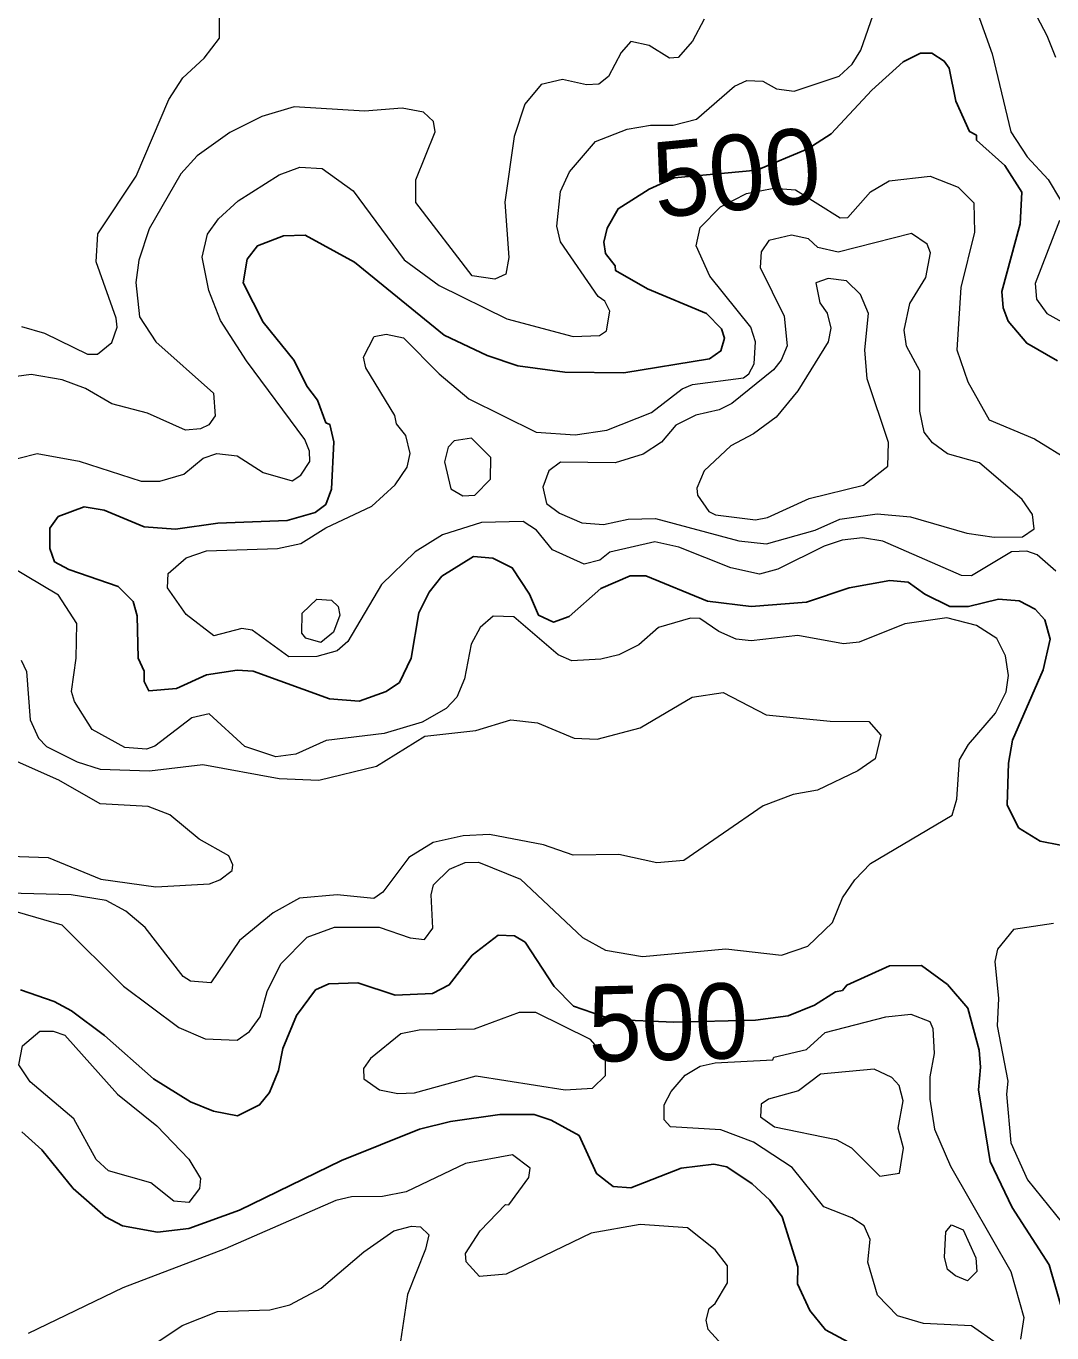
# Model space of a CAD drawing. Extents: x 763.2 to 816.8, y 7896.5 to 7952.7.
# Drawn here: x 779.613 to 781.792, y 7907.874 to 7910.648 of the extents above; entities that cross this region are included whole.
import ezdxf
from ezdxf.enums import TextEntityAlignment as Align

# ---------------------------------------------------------------- set-up
doc = ezdxf.new("R2010")
doc.units = 0
doc.header["$LTSCALE"] = 0.064
doc.layers.add('1', color=7, linetype='Continuous', lineweight=25)
doc.layers.add('2', color=7, linetype='Continuous', lineweight=13)
doc.layers.add('61', color=7, linetype='Continuous')

msp = doc.modelspace()

# ---------------------------------------------------------------- linework, layer by layer
at = {"layer": '1'}
for points in [[(781.4758, 7910.5721), (781.5125, 7910.5906), (781.5364, 7910.5906), (781.5631, 7910.5739), (781.5733, 7910.5587), (781.5874, 7910.4891), (781.617, 7910.4244), (781.6316, 7910.4166), (781.6316, 7910.4063), (781.6916, 7910.3522), (781.7276, 7910.2957), (781.7242, 7910.2285), (781.6852, 7910.0845), (781.6881, 7910.0502), (781.6986, 7910.0217), (781.7383, 7909.9751), (781.8035, 7909.9376)], [(780.9899, 7910.3261), (781.1652, 7910.342), (781.2732, 7910.3878), (781.3228, 7910.4194), (781.4094, 7910.5124), (781.4758, 7910.5721)], [(781.7665, 7908.9181), (781.7206, 7908.9465), (781.6966, 7908.9952), (781.6997, 7909.0835), (781.7079, 7909.1324), (781.7734, 7909.2819), (781.788, 7909.3466), (781.7765, 7909.3879), (781.756, 7909.4103), (781.7219, 7909.4284), (781.6784, 7909.432), (781.6145, 7909.4161), (781.5748, 7909.4161), (781.5219, 7909.4424), (781.4867, 7909.4678), (781.4476, 7909.4714), (781.3612, 7909.4555), (781.2708, 7909.4256), (781.1533, 7909.4158), (781.0605, 7909.4272), (780.9297, 7909.4811), (780.8962, 7909.4814), (780.8335, 7909.4543), (780.7668, 7909.3949), (780.733, 7909.3829), (780.7013, 7909.3974), (780.6822, 7909.4425), (780.6457, 7909.4982), (780.6043, 7909.5189), (780.5637, 7909.5225), (780.4964, 7909.4806), (780.469, 7909.4468), (780.4472, 7909.4026), (780.4311, 7909.3064), (780.4061, 7909.2548), (780.3781, 7909.2358), (780.3209, 7909.2154), (780.2578, 7909.2204), (780.0957, 7909.2787), (780.0613, 7909.2809), (779.9963, 7909.2712), (779.9331, 7909.2417), (779.874, 7909.2374), (779.8642, 7909.2571), (779.8639, 7909.2787), (779.8512, 7909.3064), (779.8494, 7909.396), (779.8408, 7909.427), (779.809, 7909.4587), (779.7038, 7909.4944), (779.6739, 7909.5111), (779.6636, 7909.5391), (779.6637, 7909.5825), (779.6817, 7909.6073), (779.7366, 7909.6276), (779.7792, 7909.6207), (779.8642, 7909.585), (779.9306, 7909.5801), (780.0202, 7909.5933), (780.1681, 7909.5984), (780.2273, 7909.6157), (780.2501, 7909.6328), (780.2616, 7909.6655), (780.2666, 7909.7657), (780.2587, 7909.8024), (780.2502, 7909.806), (780.2324, 7909.8538), (780.2092, 7909.8841), (780.1827, 7909.9382), (780.1171, 7910.02), (780.0745, 7910.1034), (780.0828, 7910.1535), (780.1045, 7910.1817), (780.16, 7910.2027), (780.2059, 7910.2043), (780.311, 7910.147), (780.5008, 7909.9922), (780.5923, 7909.9488), (780.6579, 7909.9272), (780.7574, 7909.9137), (780.883, 7909.9121), (781.0643, 7909.9422), (781.0883, 7909.9586), (781.0963, 7909.986), (781.0898, 7910.0054), (781.0585, 7910.0384), (780.933, 7910.0908), (780.8653, 7910.1292), (780.8644, 7910.1394), (780.8438, 7910.1653), (780.8404, 7910.1897), (780.847, 7910.2194), (780.8705, 7910.2605), (780.9363, 7910.3017), (780.9899, 7910.3261)], [(781.8962, 7908.8928), (781.7665, 7908.9181)], [(780.1495, 7908.4314), (780.1585, 7908.4781), (780.1873, 7908.548), (780.2281, 7908.6024), (780.2559, 7908.6153), (780.3176, 7908.617), (780.3973, 7908.5908), (780.4761, 7908.5944), (780.5121, 7908.6127), (780.5609, 7908.6761), (780.6159, 7908.7187), (780.6508, 7908.7169), (780.6729, 7908.7038), (780.7347, 7908.6094), (780.7756, 7908.5676), (780.8579, 7908.5396), (780.9891, 7908.5338), (781.1625, 7908.5377), (781.2319, 7908.5472), (781.2873, 7908.5695), (781.3318, 7908.598), (781.3467, 7908.6012), (781.3559, 7908.6126), (781.4468, 7908.653), (781.5145, 7908.6541), (781.57, 7908.6137), (781.6134, 7908.5638), (781.6373, 7908.474), (781.6402, 7908.438), (781.6357, 7908.3902), (781.6603, 7908.2381), (781.7072, 7908.1402), (781.7858, 7908.0188), (781.8159, 7907.915)], [(779.6012, 7908.6022), (779.6727, 7908.5777), (779.7096, 7908.5578), (779.7796, 7908.5057), (779.8839, 7908.4133), (779.9627, 7908.3649), (780.0113, 7908.3445), (780.0623, 7908.3346), (780.1091, 7908.3581), (780.1306, 7908.3844), (780.1495, 7908.4314)], [(781.3597, 7907.8545), (781.3106, 7907.8809), (781.2775, 7907.9219), (781.2514, 7907.9782), (781.2525, 7908.0145), (781.2188, 7908.1206), (781.1926, 7908.1561), (781.155, 7908.1903), (781.1011, 7908.2267), (781.0739, 7908.2323), (781.0047, 7908.224), (780.8978, 7908.1819), (780.8601, 7908.185), (780.8244, 7908.2124), (780.7875, 7908.2931), (780.7285, 7908.326), (780.6924, 7908.3375), (780.6193, 7908.3375), (780.5149, 7908.3227), (780.4491, 7908.3063), (780.2832, 7908.2399), (780.0663, 7908.1348), (779.9587, 7908.0958), (779.8921, 7908.088), (779.8178, 7908.1017), (779.782, 7908.1207), (779.7134, 7908.1809), (779.6465, 7908.2625), (779.6044, 7908.3013)]]:
    msp.add_lwpolyline(points, dxfattribs=at)
at = {"layer": '2'}
for points in [[(781.7998, 7910.5816), (781.7816, 7910.6276), (781.7046, 7910.7748)], [(779.6037, 7910.0107), (779.6528, 7909.9964), (779.7437, 7909.9515), (779.7653, 7909.9517), (779.7957, 7909.9767), (779.8065, 7910.0092), (779.8049, 7910.0281), (779.7619, 7910.1481), (779.7657, 7910.2071), (779.8468, 7910.3297), (779.9167, 7910.4921), (779.9463, 7910.5381), (779.9916, 7910.5804), (780.0241, 7910.6223), (780.0242, 7910.6713)], [(780.0265, 7910.0233), (780.0015, 7910.0868), (779.9874, 7910.1576), (779.9989, 7910.2062), (780.0219, 7910.2389), (780.0636, 7910.2775), (780.1511, 7910.3323), (780.1944, 7910.349), (780.242, 7910.3457), (780.3078, 7910.2982), (780.4161, 7910.1521), (780.4903, 7910.0978), (780.6343, 7910.0265), (780.7752, 7909.9892), (780.8309, 7909.9913), (780.846, 7910.0014), (780.8528, 7910.0428), (780.842, 7910.0643), (780.8279, 7910.0745), (780.7481, 7910.1904), (780.7401, 7910.2233), (780.7485, 7910.2974), (780.7672, 7910.3388), (780.8227, 7910.4032), (780.8896, 7910.4296), (780.9396, 7910.4379), (780.9876, 7910.4379), (781.0369, 7910.4508), (781.1175, 7910.5204), (781.144, 7910.5329), (781.1779, 7910.5315), (781.2066, 7910.5148), (781.2446, 7910.5103), (781.3398, 7910.5416), (781.3675, 7910.5674), (781.3859, 7910.5974), (781.4172, 7910.686)], [(781.6306, 7910.6844), (781.6646, 7910.5896), (781.7046, 7910.4239), (781.7393, 7910.3706), (781.7834, 7910.3228), (781.8097, 7910.2785)], [(781.0533, 7910.6626), (781.0288, 7910.6165), (780.9978, 7910.5816), (780.9799, 7910.58), (780.9365, 7910.6072), (780.8975, 7910.6153), (780.8768, 7910.5921), (780.85, 7910.5415), (780.8297, 7910.5251), (780.8037, 7910.5234), (780.7527, 7910.5349), (780.7069, 7910.5244), (780.6723, 7910.4827), (780.6498, 7910.4139), (780.63, 7910.2745), (780.6382, 7910.1569), (780.6321, 7910.1218), (780.6089, 7910.1109), (780.5609, 7910.1182), (780.441, 7910.2739), (780.4412, 7910.3221), (780.482, 7910.4237), (780.4788, 7910.4455), (780.4571, 7910.4654), (780.4123, 7910.474), (780.3318, 7910.4676), (780.1825, 7910.477), (780.114, 7910.456), (780.0462, 7910.4221), (779.9763, 7910.3727), (779.942, 7910.3347), (779.875, 7910.2179), (779.8528, 7910.151), (779.8462, 7910.1036), (779.8544, 7910.031), (779.8888, 7909.9776), (780.0116, 7909.869), (780.0152, 7909.8212), (780.0013, 7909.8017), (779.9834, 7909.7932), (779.9517, 7909.7907), (779.8713, 7909.8262), (779.7955, 7909.8462), (779.7392, 7909.879), (779.6899, 7909.8972), (779.6239, 7909.9088), (779.5772, 7909.9021)], [(781.7997, 7909.4909), (781.7604, 7909.5258), (781.7384, 7909.5337), (781.7059, 7909.5319), (781.621, 7909.4815), (781.5997, 7909.4817), (781.4326, 7909.5551), (781.3897, 7909.562), (781.3464, 7909.557), (781.3084, 7909.5443), (781.2098, 7909.4952), (781.1704, 7909.485), (781.1098, 7909.4979), (780.9996, 7909.5422), (780.9487, 7909.5537), (780.853, 7909.5311), (780.8318, 7909.5144), (780.7984, 7909.5063), (780.7315, 7909.5362), (780.6972, 7909.5784), (780.6691, 7909.5962), (780.5807, 7909.5947), (780.4978, 7909.5681), (780.4394, 7909.5323), (780.3679, 7909.4628), (780.2963, 7909.3418), (780.274, 7909.3219), (780.2307, 7909.3103), (780.1711, 7909.3093), (780.0935, 7909.3662), (780.0714, 7909.3693), (780.0122, 7909.3535), (779.9533, 7909.3989), (779.9135, 7909.456), (779.9154, 7909.486), (779.9535, 7909.5194), (779.9963, 7909.534), (780.147, 7909.5394), (780.1971, 7909.5497), (780.2497, 7909.5829), (780.3472, 7909.6294), (780.3969, 7909.6743), (780.4227, 7909.7119), (780.4292, 7909.7408), (780.4199, 7909.7793), (780.3997, 7909.8042), (780.3962, 7909.8215), (780.3345, 7909.9229), (780.3299, 7909.9457), (780.3526, 7909.989), (780.3783, 7909.994), (780.4146, 7909.9866), (780.4908, 7909.9099), (780.5538, 7909.8566), (780.6967, 7909.7863), (780.7793, 7909.7806), (780.8468, 7909.7904), (780.9416, 7909.8278), (781.0068, 7909.8782), (781.0286, 7909.8873), (781.1365, 7909.9018), (781.1484, 7909.9103), (781.1594, 7909.9309), (781.1624, 7909.978), (781.1524, 7910.0089), (781.0655, 7910.1175), (781.0363, 7910.1818), (781.0445, 7910.2209), (781.0879, 7910.2644), (781.1434, 7910.2927), (781.2011, 7910.3041), (781.2471, 7910.3005), (781.3418, 7910.241), (781.3582, 7910.2422), (781.4063, 7910.2967), (781.4459, 7910.32), (781.5332, 7910.3294), (781.5927, 7910.3065), (781.6258, 7910.2728), (781.6276, 7910.2109), (781.5983, 7910.0934), (781.5897, 7909.9609), (781.6131, 7909.8933), (781.6585, 7909.8126), (781.7546, 7909.7719), (781.8301, 7909.7256)], [(781.808, 7910.2353), (781.7559, 7910.1017), (781.7591, 7910.0682), (781.7809, 7910.0382), (781.8573, 7909.9958)], [(780.197, 7909.6947), (780.2156, 7909.7242), (780.2155, 7909.7459), (780.2056, 7909.7705), (780.0815, 7909.9377), (780.0265, 7910.0233)], [(779.5589, 7909.7214), (779.6367, 7909.7409), (779.726, 7909.7246), (779.8577, 7909.682), (779.8976, 7909.6822), (779.9482, 7909.6968), (779.9892, 7909.7311), (780.0186, 7909.741), (780.0613, 7909.7359), (780.1167, 7909.7004), (780.1782, 7909.6828), (780.197, 7909.6947)], [(780.0619, 7908.4956), (780.0878, 7908.5138), (780.1105, 7908.5454), (780.1254, 7908.5989), (780.1546, 7908.6574), (780.2105, 7908.7142), (780.2684, 7908.7353), (780.3631, 7908.7354), (780.4288, 7908.7125), (780.4593, 7908.7095), (780.4769, 7908.7332), (780.4738, 7908.8043), (780.4788, 7908.8256), (780.5128, 7908.8586), (780.5456, 7908.8729), (780.5739, 7908.8731), (780.6635, 7908.8374), (780.7948, 7908.7133), (780.8435, 7908.6863), (780.9225, 7908.6729), (781.0993, 7908.6891), (781.2177, 7908.6762), (781.2735, 7908.6952), (781.3261, 7908.745), (781.3473, 7908.7974), (781.3732, 7908.836), (781.4062, 7908.8705), (781.5802, 7908.9731), (781.5896, 7909.007), (781.5958, 7909.0908), (781.6144, 7909.1231), (781.6716, 7909.1895), (781.6943, 7909.2352), (781.6997, 7909.2694), (781.6934, 7909.3111), (781.6748, 7909.3481), (781.6312, 7909.3759), (781.5687, 7909.3919), (781.4796, 7909.3792), (781.3826, 7909.3401), (781.3491, 7909.3369), (781.2525, 7909.3547), (781.1532, 7909.3435), (781.1212, 7909.3465), (781.0842, 7909.3627), (781.0438, 7909.3908), (781.0243, 7909.391), (780.956, 7909.3713), (780.9146, 7909.3349), (780.8718, 7909.3133), (780.8337, 7909.304), (780.7724, 7909.3006), (780.743, 7909.3135), (780.6488, 7909.3942), (780.605, 7909.3959), (780.5774, 7909.3713), (780.5583, 7909.3365), (780.5443, 7909.2629), (780.5279, 7909.2233), (780.5055, 7909.1996), (780.4544, 7909.1704), (780.3735, 7909.1462), (780.2503, 7909.1318), (780.1863, 7909.1028), (780.1434, 7909.0969), (780.0779, 7909.1186), (780.0023, 7909.1884), (779.965, 7909.1798), (779.8865, 7909.1196), (779.8692, 7909.1133), (779.8227, 7909.1166), (779.7535, 7909.1549), (779.7159, 7909.2142), (779.7098, 7909.2356), (779.7194, 7909.3063), (779.7211, 7909.38), (779.6825, 7909.4405), (779.5792, 7909.5016)], [(779.6026, 7909.3019), (779.6143, 7909.2783), (779.6222, 7909.1755), (779.6394, 7909.1368), (779.6567, 7909.1192), (779.7216, 7909.0864), (779.7706, 7909.0709), (779.8754, 7909.0674), (779.989, 7909.0804), (780.1508, 7909.0509), (780.2348, 7909.0476), (780.3577, 7909.0775), (780.4598, 7909.1412)], [(780.8261, 7909.1342), (780.9173, 7909.1583), (781.0277, 7909.2234), (781.0935, 7909.2333), (781.1846, 7909.1859), (781.3209, 7909.1725), (781.4026, 7909.172), (781.4282, 7909.1427), (781.4163, 7909.0928), (781.3795, 7909.0676), (781.2939, 7909.0262), (781.2425, 7909.0173), (781.1783, 7908.9929), (781.0103, 7908.8768), (780.9527, 7908.8718), (780.8724, 7908.8897), (780.7752, 7908.8881), (780.712, 7908.9104), (780.5977, 7908.9324), (780.5412, 7908.9292), (780.4776, 7908.9151), (780.4263, 7908.8831), (780.3707, 7908.8098), (780.3521, 7908.7963), (780.2742, 7908.8043), (780.1941, 7908.7968), (780.1382, 7908.7656), (780.0662, 7908.7073), (780.0059, 7908.6172), (779.9623, 7908.6205), (779.9472, 7908.6309), (779.8662, 7908.7348), (779.8252, 7908.7694), (779.7833, 7908.7923), (779.709, 7908.8043), (779.5768, 7908.8079)], [(780.4598, 7909.1412), (780.5682, 7909.1529), (780.6426, 7909.1755), (780.699, 7909.169), (780.7772, 7909.1366), (780.8261, 7909.1342)], [(779.4761, 7908.8899), (779.6603, 7908.8832), (779.772, 7908.8372), (779.889, 7908.8208), (780.0028, 7908.8276), (780.025, 7908.8356), (780.0511, 7908.8557), (780.0526, 7908.8674), (780.0438, 7908.8871), (779.9812, 7908.9219), (779.9185, 7908.9742), (779.8723, 7908.9916), (779.7707, 7908.9969), (779.6827, 7909.0478), (779.5952, 7909.0867)], [(779.5945, 7908.7681), (779.6893, 7908.7404), (779.8203, 7908.6099), (779.9375, 7908.5221), (779.9933, 7908.4982), (780.0619, 7908.4956)], [(781.7952, 7908.7434), (781.7098, 7908.7306), (781.6761, 7908.689), (781.6706, 7908.6627), (781.6783, 7908.5838), (781.6753, 7908.5259), (781.6979, 7908.4082), (781.6949, 7908.3812), (781.7047, 7908.2776), (781.74, 7908.1993), (781.8439, 7908.0703)], [(781.6755, 7907.851), (781.621, 7907.889), (781.5188, 7907.8939), (781.4637, 7907.9105), (781.4211, 7907.9542), (781.4007, 7908.0244), (781.4056, 7908.0724), (781.3933, 7908.1014), (781.3666, 7908.1186), (781.3072, 7908.142), (781.2402, 7908.2252), (781.1578, 7908.2791), (781.0887, 7908.305), (780.9818, 7908.3115), (780.9686, 7908.3263), (780.9685, 7908.3581), (780.9834, 7908.3868), (781.0129, 7908.4214), (781.0445, 7908.4405), (781.0763, 7908.4477), (781.199, 7908.4539), (781.2012, 7908.4592), (781.2707, 7908.4758), (781.3104, 7908.5116), (781.4392, 7908.5451), (781.4918, 7908.551), (781.5324, 7908.5354), (781.5391, 7908.5204), (781.542, 7908.4674), (781.5322, 7908.4174), (781.5321, 7908.3705), (781.5421, 7908.3064), (781.5762, 7908.2282), (781.7045, 7908.0046), (781.7323, 7907.9067), (781.7247, 7907.8607)], [(781.1287, 7907.8078), (781.0619, 7907.8811), (781.0577, 7907.9015), (781.064, 7907.9261), (781.0766, 7907.9367), (781.1027, 7907.9803), (781.1031, 7908.0164), (781.0764, 7908.0505), (781.0182, 7908.0972), (780.9177, 7908.1041), (780.8134, 7908.0858), (780.6325, 7907.999), (780.5761, 7907.9936), (780.5479, 7908.0247), (780.5467, 7908.0425), (780.5775, 7908.091), (780.6313, 7908.1468), (780.6388, 7908.1463), (780.6811, 7908.2041), (780.6838, 7908.2239), (780.6461, 7908.2518), (780.5464, 7908.2335), (780.4202, 7908.1734), (780.3702, 7908.1634), (780.3041, 7908.1632), (780.271, 7908.1549), (780.0364, 7908.0523), (779.8187, 7907.9697), (779.6175, 7907.8726)], [(779.8591, 7907.8326), (779.945, 7907.8899), (780.0201, 7907.9199), (780.1313, 7907.9232), (780.1737, 7907.9336), (780.2399, 7907.9688), (780.3303, 7908.0459), (780.3943, 7908.0907), (780.4321, 7908.1007), (780.451, 7908.0994), (780.4683, 7908.0821), (780.4618, 7908.052), (780.423, 7907.9554), (780.4062, 7907.8423)]]:
    msp.add_lwpolyline(points, dxfattribs=at)
for points in [[(781.6379, 7909.7209), (781.5697, 7909.7399), (781.5378, 7909.7637), (781.5202, 7909.7859), (781.511, 7909.8309), (781.5111, 7909.9166), (781.4832, 7909.9686), (781.4781, 7910.0026), (781.4903, 7910.0596), (781.524, 7910.1147), (781.5338, 7910.1671), (781.5267, 7910.1851), (781.4932, 7910.2076), (781.338, 7910.1685), (781.2947, 7910.1785), (781.275, 7910.1963), (781.2386, 7910.2043), (781.1904, 7910.1929), (781.1746, 7910.169), (781.1719, 7910.1357), (781.2228, 7910.0322), (781.2295, 7909.9698), (781.2167, 7909.9387), (781.2002, 7909.9186), (781.1119, 7909.8473), (781.0851, 7909.8333), (781.0354, 7909.8224), (780.9928, 7909.8009), (780.9624, 7909.7649), (780.9236, 7909.7393), (780.864, 7909.7214), (780.7485, 7909.7228), (780.7233, 7909.7042), (780.7106, 7909.6692), (780.7185, 7909.6348), (780.7461, 7909.6139), (780.7938, 7909.594), (780.8396, 7909.5899), (780.8917, 7909.6013), (780.95, 7909.6029), (781.1269, 7909.5552), (781.1855, 7909.5489), (781.2893, 7909.5779), (781.3413, 7909.6017), (781.4207, 7909.6128), (781.4911, 7909.6063), (781.6107, 7909.5717), (781.6693, 7909.5636), (781.7289, 7909.564), (781.7537, 7909.5808), (781.7505, 7909.6111), (781.7285, 7909.6433)], [(781.4434, 7909.7138), (781.445, 7909.7644), (781.3994, 7909.8991), (781.3942, 7909.9611), (781.4021, 7910.0379), (781.3854, 7910.0783), (781.3557, 7910.1074), (781.3163, 7910.1123), (781.2907, 7910.103), (781.299, 7910.0605), (781.3143, 7910.0386), (781.3219, 7910.0069), (781.3165, 7909.9781), (781.2524, 7909.8737), (781.2062, 7909.8179), (781.158, 7909.7825), (781.1099, 7909.7574), (781.0532, 7909.7044), (781.0378, 7909.6671), (781.039, 7909.6521), (781.0632, 7909.6177), (781.077, 7909.611), (781.1624, 7909.5998), (781.1877, 7909.6052), (781.2762, 7909.6451), (781.3919, 7909.6736)], [(780.5594, 7909.7735), (780.5221, 7909.7676), (780.5095, 7909.7544), (780.502, 7909.7232), (780.5153, 7909.6656), (780.5406, 7909.6511), (780.5664, 7909.6522), (780.5996, 7909.6862), (780.6002, 7909.7322)], [(780.2621, 7909.4299), (780.2761, 7909.416), (780.2798, 7909.3979), (780.266, 7909.3615), (780.239, 7909.3399), (780.2071, 7909.3487), (780.1987, 7909.3596), (780.1996, 7909.4022), (780.2306, 7909.4318)], [(780.5692, 7908.4196), (780.7581, 7908.3902), (780.8163, 7908.3935), (780.8434, 7908.4206), (780.844, 7908.4604), (780.8118, 7908.4973), (780.6956, 7908.5543), (780.6607, 7908.5541), (780.5648, 7908.5187), (780.4478, 7908.5166), (780.4092, 7908.5087), (780.3447, 7908.4565), (780.3298, 7908.4356), (780.3303, 7908.4134), (780.3639, 7908.3901), (780.4025, 7908.3821), (780.4378, 7908.3838)], [(779.7149, 7908.3288), (779.6221, 7908.4073), (779.598, 7908.4434), (779.6061, 7908.4838), (779.6425, 7908.5147), (779.6708, 7908.5148), (779.6957, 7908.5058), (779.8078, 7908.3806), (779.8909, 7908.314), (779.9589, 7908.2427), (779.9835, 7908.2018), (779.9818, 7908.1805), (779.9592, 7908.1508), (779.9273, 7908.1537), (779.878, 7908.1924), (779.7887, 7908.2179), (779.7625, 7908.2419)], [(781.3338, 7908.2848), (781.3661, 7908.2667), (781.4264, 7908.2068), (781.4683, 7908.2134), (781.4762, 7908.2662), (781.4649, 7908.3087), (781.4759, 7908.3671), (781.4673, 7908.3996), (781.4519, 7908.4162), (781.4139, 7908.4343), (781.3, 7908.4232), (781.2539, 7908.3877), (781.1901, 7908.3706), (781.1742, 7908.3597), (781.1726, 7908.3329), (781.2023, 7908.3118)], [(781.6121, 7907.9847), (781.5868, 7907.9956), (781.5697, 7908.009), (781.5634, 7908.0352), (781.5667, 7908.0884), (781.5785, 7908.1035), (781.603, 7908.0932), (781.63, 7908.0334), (781.6321, 7908.0043)]]:
    msp.add_lwpolyline(points, close=True, dxfattribs=at)

# ---------------------------------------------------------------- texts
at = {"layer": '61'}
msp.add_text('500', height=0.16, rotation=5.635, dxfattribs=at).set_placement((781.1299, 7910.2581), align=Align.CENTER)
at = {"layer": '61', "width": 0.95}
msp.add_text('500', height=0.16, rotation=1.417, dxfattribs=at).set_placement((780.9787, 7908.4535), align=Align.CENTER)

doc.saveas('drawing.dxf')
